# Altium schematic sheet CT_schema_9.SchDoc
size 391 x 238 mm
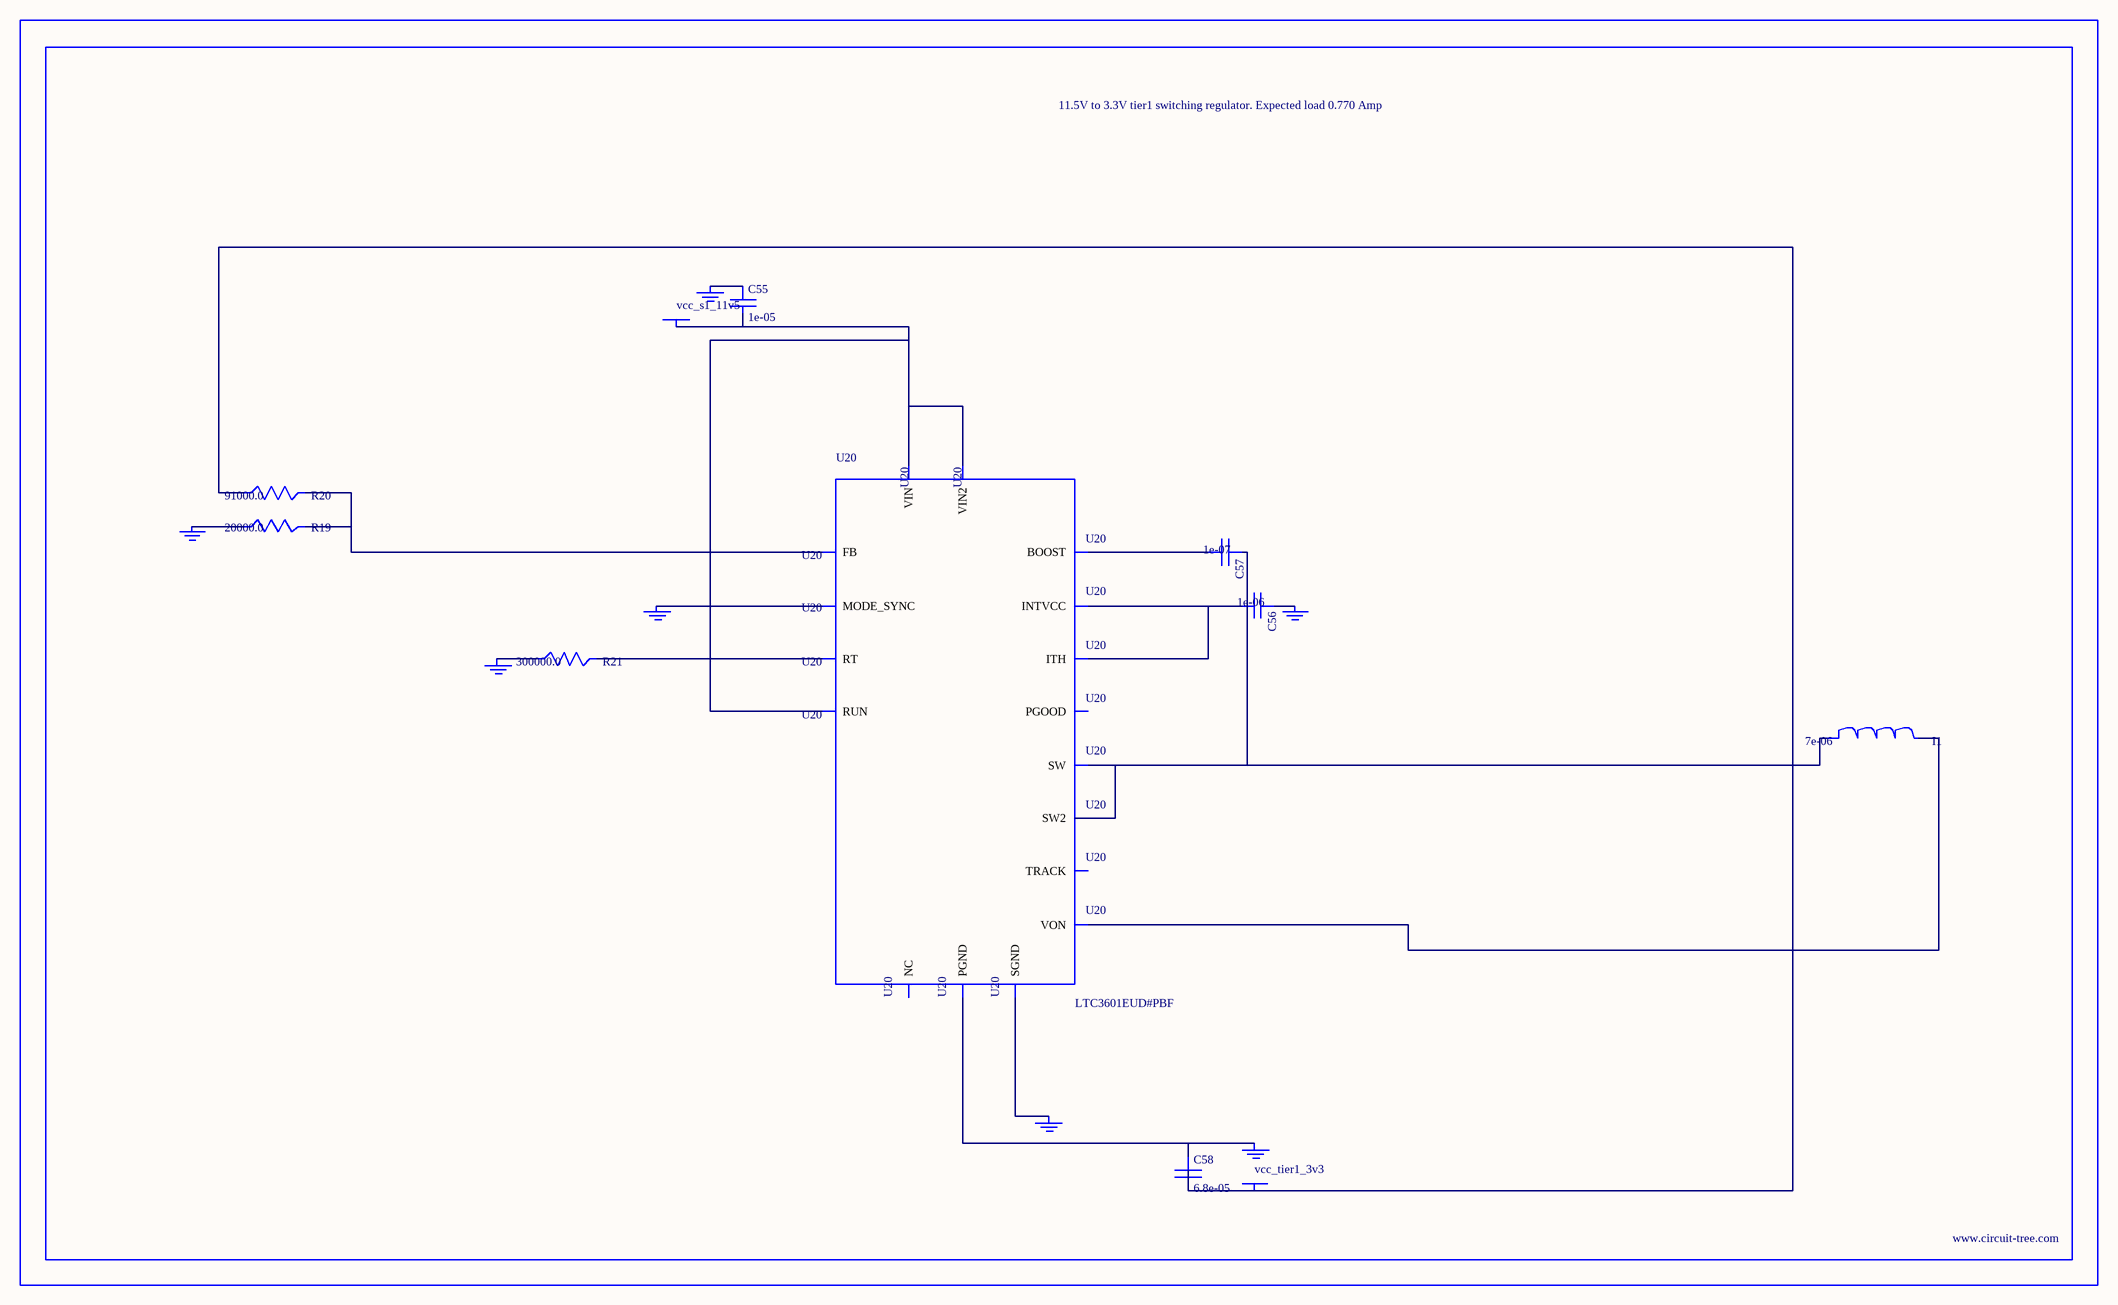
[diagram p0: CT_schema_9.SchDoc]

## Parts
BORDER8  (no value)
C55  1e-05  [C0805]
C56  1e-06  [C0603]
C57  1e-07  [C0402]
C58  6.8e-05  [2220]
GND_INSTANCE_8_0  (no value)
GND_INSTANCE_8_1  (no value)
GND_INSTANCE_8_2  (no value)
GND_INSTANCE_8_3  (no value)
GND_INSTANCE_8_4  (no value)
GND_INSTANCE_8_5  (no value)
GND_INSTANCE_8_6  (no value)
I1  7e-06  [DR1040]
POWER_INSTANCE_8_0  vcc_s1_11v5
POWER_INSTANCE_8_1  vcc_tier1_3v3
R19  20000.0  [R0603]
R20  91000.0  [R0603]
R21  300000.0  [R0603]
U20  LTC3601EUD#PBF  [QFN-16_EP]

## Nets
NetC55_1: C55.1 GND_INSTANCE_8_5.0(GND)
NetC55_2: C55.2 POWER_INSTANCE_8_0.0(PWR) U20.14(RUN) U20.15(VIN) U20.16(VIN2)
NetC56_1: C56.1 GND_INSTANCE_8_1.0(GND)
NetC56_2: C56.2 U20.7(INTVCC) U20.12(ITH)
NetC57_1: C57.1 I1.1 U20.3(SW) U20.4(SW2)
NetC57_2: C57.2 U20.6(BOOST)
NetC58_1: C58.1 GND_INSTANCE_8_6.0(GND) U20.17(PGND)
NetC58_2: C58.2 I1.2 POWER_INSTANCE_8_1.0(PWR) R20.1 U20.8(VON)
NetGND_INSTANCE_8_0_0: GND_INSTANCE_8_0.0(GND) U20.1(MODE_SYNC)
NetGND_INSTANCE_8_2_0: GND_INSTANCE_8_2.0(GND) U20.9(SGND)
NetGND_INSTANCE_8_3_0: GND_INSTANCE_8_3.0(GND) R21.1
NetGND_INSTANCE_8_4_0: GND_INSTANCE_8_4.0(GND) R19.1
NetR19_2: R19.2 R20.2 U20.11(FB)
NetR21_2: R21.2 U20.10(RT)

Not connected (* = marked no-connect by the designer): U20 2(PGOOD) 5(NC) 13(TRACK)

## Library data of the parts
BORDER8 = BORDER_PAGE8
C55 = C0805C106K8RACTU
C56 = C0603C105K3RACTU
C57 = C0402C104K3RACTU
C58 = C5750X5R1A686M
GND_INSTANCE_8_0-GND_INSTANCE_8_6 = GND
I1 = DR1040-7R0-R
POWER_INSTANCE_8_0 POWER_INSTANCE_8_1 = PWR
R19 = RC0603JR-0720KL
R20 = RC0603JR-0791KL
R21 = RC0603JR-07300KL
